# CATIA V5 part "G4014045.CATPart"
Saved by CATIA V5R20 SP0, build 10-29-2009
Part number: G4014045
Revision: 4
Definition: design
Nomenclature: G4014045
Source: made
Description: NOT SPECIFIED
Bounding box of the stored display mesh (mm): x 0 to 45, y -28 to 28, z -28 to 28
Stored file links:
  C:\Users\Raffaele\Desktop\3D X SITO CF\BOLEX\25-BUSH REF 401\G4014045.CATPart
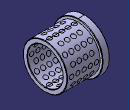
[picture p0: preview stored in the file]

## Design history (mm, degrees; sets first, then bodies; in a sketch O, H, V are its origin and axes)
Body1 "MANIFOLD_SOLID_BREP #10625" (main body)
  Solid1: solid without history
Body2 "MANIFOLD_SOLID_BREP #10778"
  Solid2: solid without history
Body3 "MANIFOLD_SOLID_BREP #10931"
  Solid3: solid without history
Body4 "MANIFOLD_SOLID_BREP #11084"
  Solid4: solid without history
Body5 "MANIFOLD_SOLID_BREP #11237"
  Solid5: solid without history
Body6 "MANIFOLD_SOLID_BREP #11396"
  Solid6: solid without history
Body7 "MANIFOLD_SOLID_BREP #11555"
  Solid7: solid without history
Body8 "MANIFOLD_SOLID_BREP #11716"
  Solid8: solid without history
Body9 "MANIFOLD_SOLID_BREP #11877"
  Solid9: solid without history
Body10 "MANIFOLD_SOLID_BREP #12036"
  Solid10: solid without history
Body11 "MANIFOLD_SOLID_BREP #12195"
  Solid11: solid without history
Body12 "MANIFOLD_SOLID_BREP #12354"
  Solid12: solid without history
Body13 "MANIFOLD_SOLID_BREP #12513"
  Solid13: solid without history
Body14 "MANIFOLD_SOLID_BREP #12674"
  Solid14: solid without history
Body15 "MANIFOLD_SOLID_BREP #12835"
  Solid15: solid without history
Body16 "MANIFOLD_SOLID_BREP #12994"
  Solid16: solid without history
Body17 "MANIFOLD_SOLID_BREP #13153"
  Solid17: solid without history
Body18 "MANIFOLD_SOLID_BREP #13314"
  Solid18: solid without history
Body19 "MANIFOLD_SOLID_BREP #13475"
  Solid19: solid without history
Body20 "MANIFOLD_SOLID_BREP #13636"
  Solid20: solid without history
Body21 "MANIFOLD_SOLID_BREP #13797"
  Solid21: solid without history
Body22 "MANIFOLD_SOLID_BREP #13958"
  Solid22: solid without history
Body23 "MANIFOLD_SOLID_BREP #14119"
  Solid23: solid without history
Body24 "MANIFOLD_SOLID_BREP #14280"
  Solid24: solid without history
Body25 "MANIFOLD_SOLID_BREP #14441"
  Solid25: solid without history
Body26 "MANIFOLD_SOLID_BREP #14594"
  Solid26: solid without history
Body27 "MANIFOLD_SOLID_BREP #14747"
  Solid27: solid without history
Body28 "MANIFOLD_SOLID_BREP #14906"
  Solid28: solid without history
Body29 "MANIFOLD_SOLID_BREP #15067"
  Solid29: solid without history
Body30 "MANIFOLD_SOLID_BREP #15226"
  Solid30: solid without history
Body31 "MANIFOLD_SOLID_BREP #15385"
  Solid31: solid without history
Body32 "MANIFOLD_SOLID_BREP #15546"
  Solid32: solid without history
Body33 "MANIFOLD_SOLID_BREP #15705"
  Solid33: solid without history
Body34 "MANIFOLD_SOLID_BREP #15866"
  Solid34: solid without history
Body35 "MANIFOLD_SOLID_BREP #16027"
  Solid35: solid without history
Body36 "MANIFOLD_SOLID_BREP #16188"
  Solid36: solid without history
Body37 "MANIFOLD_SOLID_BREP #16349"
  Solid37: solid without history
Body38 "MANIFOLD_SOLID_BREP #16510"
  Solid38: solid without history
Body39 "MANIFOLD_SOLID_BREP #16671"
  Solid39: solid without history
Body40 "MANIFOLD_SOLID_BREP #16832"
  Solid40: solid without history
Body41 "MANIFOLD_SOLID_BREP #16993"
  Solid41: solid without history
Body42 "MANIFOLD_SOLID_BREP #17146"
  Solid42: solid without history
Body43 "MANIFOLD_SOLID_BREP #17299"
  Solid43: solid without history
Body44 "MANIFOLD_SOLID_BREP #17458"
  Solid44: solid without history
Body45 "MANIFOLD_SOLID_BREP #17619"
  Solid45: solid without history
Body46 "MANIFOLD_SOLID_BREP #17778"
  Solid46: solid without history
Body47 "MANIFOLD_SOLID_BREP #17937"
  Solid47: solid without history
Body48 "MANIFOLD_SOLID_BREP #18098"
  Solid48: solid without history
Body49 "MANIFOLD_SOLID_BREP #18257"
  Solid49: solid without history
Body50 "MANIFOLD_SOLID_BREP #18418"
  Solid50: solid without history
Body51 "MANIFOLD_SOLID_BREP #18579"
  Solid51: solid without history
Body52 "MANIFOLD_SOLID_BREP #18740"
  Solid52: solid without history
Body53 "MANIFOLD_SOLID_BREP #18901"
  Solid53: solid without history
Body54 "MANIFOLD_SOLID_BREP #19062"
  Solid54: solid without history
Body55 "MANIFOLD_SOLID_BREP #19223"
  Solid55: solid without history
Body56 "MANIFOLD_SOLID_BREP #19384"
  Solid56: solid without history
Body57 "MANIFOLD_SOLID_BREP #19545"
  Solid57: solid without history
Body58 "MANIFOLD_SOLID_BREP #19698"
  Solid58: solid without history
Body59 "MANIFOLD_SOLID_BREP #19851"
  Solid59: solid without history
Body60 "MANIFOLD_SOLID_BREP #20010"
  Solid60: solid without history
Body61 "MANIFOLD_SOLID_BREP #20171"
  Solid61: solid without history
Body62 "MANIFOLD_SOLID_BREP #20330"
  Solid62: solid without history
Body63 "MANIFOLD_SOLID_BREP #20489"
  Solid63: solid without history
Body64 "MANIFOLD_SOLID_BREP #20650"
  Solid64: solid without history
Body65 "MANIFOLD_SOLID_BREP #20809"
  Solid65: solid without history
Body66 "MANIFOLD_SOLID_BREP #20970"
  Solid66: solid without history
Body67 "MANIFOLD_SOLID_BREP #21131"
  Solid67: solid without history
Body68 "MANIFOLD_SOLID_BREP #21292"
  Solid68: solid without history
Body69 "MANIFOLD_SOLID_BREP #21453"
  Solid69: solid without history
Body70 "MANIFOLD_SOLID_BREP #21614"
  Solid70: solid without history
Body71 "MANIFOLD_SOLID_BREP #21775"
  Solid71: solid without history
Body72 "MANIFOLD_SOLID_BREP #21936"
  Solid72: solid without history
Body73 "MANIFOLD_SOLID_BREP #22097"
  Solid73: solid without history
